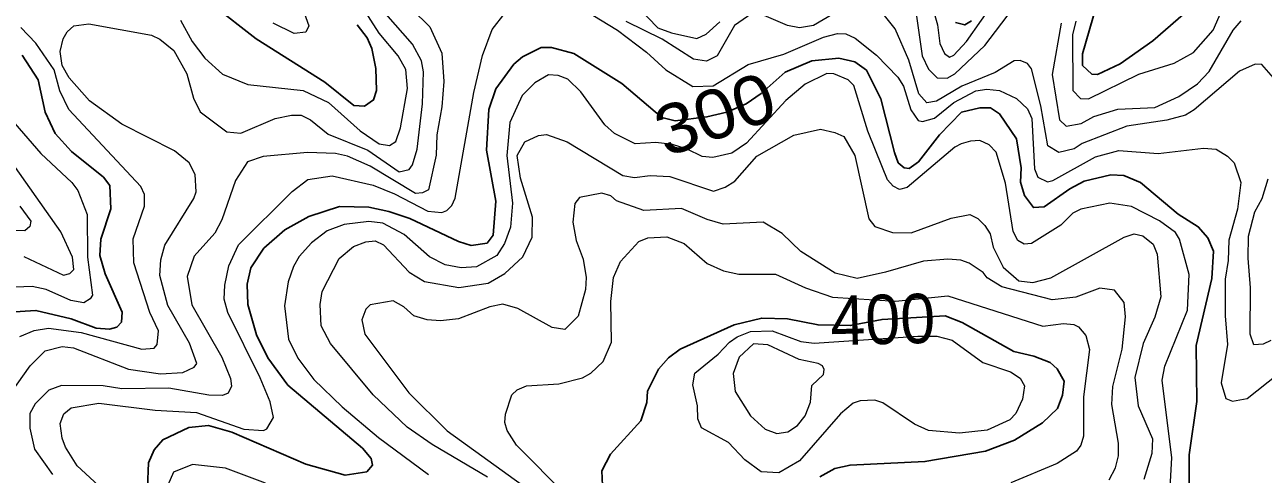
# Model space of a CAD drawing. Extents: x 673.6 to 698.9, y 7012 to 7040.1.
# Drawn here: x 691.831 to 693.836, y 7013.382 to 7014.11 of the extents above; entities that cross this region are included whole.
import ezdxf
from ezdxf.enums import TextEntityAlignment as Align

# ---------------------------------------------------------------- set-up
doc = ezdxf.new("R2010")
doc.units = 0
doc.header["$LTSCALE"] = 0.032
doc.layers.add('1', color=7, linetype='Continuous', lineweight=25)
doc.layers.add('2', color=7, linetype='Continuous', lineweight=13)
doc.layers.add('61', color=7, linetype='Continuous')

msp = doc.modelspace()

# ---------------------------------------------------------------- linework, layer by layer
at = {"layer": '1'}
for points in [[(693.7393, 7014.1557), (693.6572, 7014.0842), (693.6043, 7014.0469), (693.5677, 7014.0298), (693.5587, 7014.0301), (693.5438, 7014.0441), (693.5436, 7014.063), (693.5781, 7014.1829)], [(692.3692, 7014.1102), (692.3856, 7014.0888), (692.393, 7014.0715), (692.3996, 7014.0396), (692.4005, 7014.0035), (692.3956, 7013.9884), (692.3814, 7013.9783), (692.3638, 7013.9795), (692.3168, 7014.017), (692.2057, 7014.0872), (692.1352, 7014.1427)], [(693.3637, 7014.1164), (693.3529, 7014.11), (693.3378, 7014.1141)], [(693.0232, 7013.9989), (692.999, 7013.9821), (692.9679, 7013.9686), (692.9354, 7013.961), (692.884, 7013.9546), (692.8626, 7013.9598), (692.7977, 7014.015), (692.7201, 7014.0634), (692.684, 7014.0732), (692.6673, 7014.0732), (692.6371, 7014.0581), (692.623, 7014.0466), (692.594, 7014.0065), (692.5822, 7013.973), (692.5788, 7013.9068), (692.5936, 7013.8247), (692.5896, 7013.7694), (692.5796, 7013.7563), (692.5537, 7013.7529), (692.5336, 7013.7591), (692.4543, 7013.7962), (692.4207, 7013.8079), (692.3884, 7013.8146), (692.3405, 7013.816), (692.2909, 7013.7995), (692.2524, 7013.7779), (692.2183, 7013.7481), (692.1972, 7013.7165), (692.191, 7013.6899), (692.1925, 7013.657), (692.2064, 7013.6077), (692.2248, 7013.5709), (692.2571, 7013.5263), (692.3777, 7013.4246), (692.392, 7013.4079), (692.3939, 7013.3969), (692.3848, 7013.386), (692.35, 7013.3806), (692.2862, 7013.3986), (692.1664, 7013.4504), (692.1284, 7013.4612), (692.0966, 7013.4576), (692.0546, 7013.438), (692.0406, 7013.4215), (692.0317, 7013.4006), (692.0299, 7013.3608)], [(691.8269, 7014.0609), (691.853, 7014.0208), (691.864, 7013.9686), (691.8806, 7013.934), (691.9069, 7013.9051), (691.9585, 7013.8636), (691.9689, 7013.8497), (691.9707, 7013.8123), (691.9542, 7013.7631), (691.9527, 7013.7367), (691.9614, 7013.7069), (691.989, 7013.6447), (691.9875, 7013.6283), (691.9801, 7013.6204), (691.9685, 7013.617), (691.9465, 7013.6187), (691.906, 7013.6339), (691.8491, 7013.6476), (691.8065, 7013.6446)], [(693.7162, 7013.3668), (693.7162, 7013.4138), (693.7284, 7013.5001), (693.7277, 7013.5909), (693.7531, 7013.6994), (693.7555, 7013.7433), (693.7465, 7013.7651), (693.7309, 7013.7831), (693.6986, 7013.8032), (693.6372, 7013.8549), (693.6105, 7013.8662), (693.5895, 7013.867), (693.5461, 7013.8566), (693.523, 7013.8443), (693.4814, 7013.8155), (693.4641, 7013.814), (693.4495, 7013.8334), (693.4433, 7013.8555), (693.4441, 7013.8785), (693.4365, 7013.9255), (693.409, 7013.9661), (693.3944, 7013.9754), (693.3775, 7013.9754), (693.3477, 7013.9686), (693.312, 7013.932), (693.2778, 7013.8881), (693.2627, 7013.8772), (693.2547, 7013.8784), (693.2452, 7013.8867), (693.2394, 7013.9035), (693.2173, 7013.9902), (693.1936, 7014.0369), (693.175, 7014.0503), (693.1491, 7014.056), (693.1055, 7014.0516), (693.0624, 7014.0332), (693.0232, 7013.9989)], [(693.1183, 7013.3782), (693.1426, 7013.3912), (693.1672, 7013.3969), (693.2884, 7013.4027), (693.3867, 7013.4194), (693.4334, 7013.4373), (693.4789, 7013.4654), (693.503, 7013.4887), (693.5114, 7013.51), (693.5138, 7013.5329), (693.5024, 7013.553), (693.4912, 7013.5629), (693.465, 7013.5735), (693.4326, 7013.5807), (693.349, 7013.6282), (693.3214, 7013.6387), (693.2191, 7013.633), (693.1676, 7013.6229), (693.1156, 7013.6241), (693.0658, 7013.634), (693.0243, 7013.6352), (692.9797, 7013.624), (692.8924, 7013.5849), (692.8733, 7013.5706), (692.8569, 7013.5522), (692.8395, 7013.5169), (692.8383, 7013.4985), (692.8287, 7013.4688), (692.7796, 7013.4145), (692.7656, 7013.3875), (692.7667, 7013.3641)]]:
    msp.add_lwpolyline(points, dxfattribs=at)
at = {"layer": '2'}
for points in [[(692.3855, 7014.2132), (692.3997, 7014.1931), (692.4867, 7014.1069), (692.5064, 7014.0643), (692.5097, 7014.0182), (692.5065, 7013.9771)], [(693.2832, 7014.1987), (693.3086, 7014.1099), (693.3124, 7014.0799), (693.3203, 7014.0639), (693.3283, 7014.0578), (693.3351, 7014.0612), (693.3557, 7014.0833), (693.4043, 7014.1529)], [(692.7735, 7014.1908), (692.8562, 7014.1054), (692.878, 7014.0971), (692.9194, 7014.0882), (692.9341, 7014.095), (692.9566, 7014.1149)], [(693.261, 7014.1664), (693.274, 7014.1316), (693.2842, 7014.0597), (693.2942, 7014.0384), (693.3084, 7014.0242), (693.3246, 7014.0239)], [(692.0833, 7014.1176), (692.1019, 7014.083), (692.1225, 7014.0563), (692.1512, 7014.0299), (692.1923, 7014.0133), (692.2817, 7014.0036), (692.3227, 7013.9843), (692.3744, 7013.9382), (692.4049, 7013.9172), (692.4215, 7013.9147), (692.432, 7013.921), (692.4393, 7013.9434), (692.4506, 7014.0067), (692.4483, 7014.0378), (692.4356, 7014.0596), (692.4051, 7014.0968), (692.378, 7014.1386)], [(692.2758, 7014.151), (692.2911, 7014.1085), (692.286, 7014.098), (692.2672, 7014.0959), (692.2334, 7014.1129)], [(692.7382, 7014.1332), (692.791, 7014.1017), (692.8379, 7014.0656), (692.869, 7014.0371), (692.9128, 7014.01), (692.9456, 7014.0112), (693.0025, 7014.046), (693.0598, 7014.0628), (693.124, 7014.09), (693.1471, 7014.0961), (693.1605, 7014.0954), (693.1753, 7014.0887), (693.2102, 7014.0607), (693.2447, 7014.0255), (693.2537, 7014.0109), (693.2655, 7013.9726), (693.2776, 7013.9549), (693.2847, 7013.9535), (693.3042, 7013.9589), (693.3355, 7013.9841), (693.371, 7014.0034), (693.3885, 7014.0059), (693.4091, 7014.0037), (693.4367, 7013.991), (693.4544, 7013.974), (693.4613, 7013.9583), (693.4661, 7013.8766), (693.4714, 7013.8635), (693.4871, 7013.8557), (693.4953, 7013.8577), (693.5646, 7013.8965), (693.6024, 7013.9064), (693.6659, 7013.9016), (693.7395, 7013.9105), (693.7602, 7013.9086), (693.7783, 7013.8975), (693.7893, 7013.8864), (693.8, 7013.8548), (693.7943, 7013.8115), (693.7803, 7013.7615), (693.7795, 7013.7281), (693.7744, 7013.6982), (693.7745, 7013.639), (693.7785, 7013.5925), (693.7678, 7013.53), (693.7757, 7013.5048), (693.7865, 7013.5006), (693.8099, 7013.5048), (693.9094, 7013.5839)], [(693.3246, 7014.0239), (693.3368, 7014.0309), (693.3852, 7014.0768), (693.4304, 7014.1352)], [(693.5326, 7014.1162), (693.5276, 7014.0939), (693.528, 7014.0038), (693.5402, 7013.991), (693.5535, 7013.9902), (693.635, 7014.0302), (693.6921, 7014.0481), (693.7235, 7014.0651), (693.7553, 7014.1017), (693.7762, 7014.1497)], [(692.1052, 7013.5556), (692.1095, 7013.5616), (692.098, 7013.5946), (692.0626, 7013.6554), (692.0497, 7013.7043), (692.0513, 7013.7293), (692.0577, 7013.7533), (692.105, 7013.8287), (692.1087, 7013.8395), (692.1071, 7013.8675), (692.0971, 7013.8867), (692.0737, 7013.9062), (691.9882, 7013.9493), (691.9357, 7013.9869), (691.903, 7014.0241), (691.8919, 7014.044), (691.8887, 7014.0669), (691.8935, 7014.0872), (691.9, 7014.0987), (691.9108, 7014.1086), (691.9346, 7014.1118), (692.0361, 7014.0931), (692.05, 7014.087), (692.0725, 7014.0683), (692.0934, 7014.0306), (692.1041, 7013.9912), (692.1152, 7013.9693), (692.1585, 7013.9368), (692.1812, 7013.9346), (692.2366, 7013.9581), (692.2632, 7013.9639), (692.2785, 7013.9639), (692.2936, 7013.9563), (692.3224, 7013.9328), (692.3865, 7013.9072), (692.4372, 7013.8722), (692.4535, 7013.876), (692.4587, 7013.8834), (692.4663, 7013.9085), (692.4752, 7013.9821), (692.4768, 7014.0338), (692.4736, 7014.0516), (692.459, 7014.0788), (692.4156, 7014.128)], [(692.5879, 7014.1025), (692.6087, 7014.1294)], [(693.008, 7014.1283), (692.9802, 7014.1088), (692.9523, 7014.0601), (692.9351, 7014.0511), (692.9139, 7014.0545), (692.8628, 7014.0866), (692.8046, 7014.1156)], [(693.1393, 7014.1274), (693.1083, 7014.1088), (693.0854, 7014.1054), (693.066, 7014.1092), (693.0206, 7014.1283)], [(693.8528, 7014.0241), (693.8338, 7014.0459), (693.823, 7014.0461), (693.7977, 7014.035), (693.7246, 7013.9725), (693.7102, 7013.9636), (693.6803, 7013.9558), (693.6155, 7013.9458), (693.543, 7013.9176), (693.53, 7013.9093), (693.5054, 7013.9033), (693.4876, 7013.9142), (693.4761, 7013.9787), (693.4612, 7014.0387), (693.4545, 7014.0475), (693.4428, 7014.0525), (693.4328, 7014.0516), (693.402, 7014.0329), (693.348, 7014.0108), (693.3072, 7013.9863), (693.2913, 7013.9837), (693.2784, 7013.9982), (693.2624, 7014.053), (693.2405, 7014.1037), (693.2228, 7014.1253)], [(693.5089, 7014.1127), (693.4943, 7014.0294), (693.5065, 7013.9561), (693.5169, 7013.946), (693.5416, 7013.95), (693.562, 7013.9616), (693.6007, 7013.9737), (693.6605, 7013.9764), (693.6994, 7013.9942), (693.7295, 7014.0143), (693.7487, 7014.0347), (693.7875, 7014.1017), (693.8003, 7014.1164)], [(691.8231, 7013.6055), (691.8462, 7013.6148), (691.8696, 7013.6187), (691.9227, 7013.6115), (692.0209, 7013.5845), (692.0404, 7013.5865), (692.0454, 7013.5921), (692.0478, 7013.6144), (692.0334, 7013.6444), (692.0076, 7013.7244), (692.0069, 7013.7634), (692.0249, 7013.8161), (692.0249, 7013.8352), (692.0191, 7013.8484), (691.9026, 7013.9727), (691.8879, 7014.0031), (691.8786, 7014.0371), (691.8491, 7014.0806), (691.8247, 7014.1059)], [(692.5147, 7013.8095), (692.5226, 7013.8175), (692.528, 7013.8291), (692.5582, 7014.0006), (692.5723, 7014.0606), (692.5879, 7014.1025)], [(692.6571, 7014.016), (692.6364, 7013.9954), (692.6165, 7013.9521), (692.6117, 7013.8986), (692.6207, 7013.821), (692.6175, 7013.7823), (692.6079, 7013.756), (692.5952, 7013.7366), (692.5627, 7013.718), (692.5374, 7013.7167), (692.5118, 7013.7215), (692.4864, 7013.7341), (692.4455, 7013.7703), (692.4109, 7013.789), (692.388, 7013.7915), (692.3483, 7013.7867), (692.3205, 7013.7764), (692.2956, 7013.7572), (692.2756, 7013.7349), (692.2664, 7013.7188), (692.2578, 7013.6936), (692.2518, 7013.6547), (692.2583, 7013.6011), (692.273, 7013.5701), (692.2989, 7013.5355), (692.3448, 7013.4912), (692.404, 7013.4419), (692.4845, 7013.3819)], [(692.7705, 7013.9482), (692.7316, 7014.0016), (692.7102, 7014.0221), (692.6949, 7014.0282), (692.6793, 7014.0289), (692.6571, 7014.016)], [(693.6857, 7013.3608), (693.6882, 7013.4087), (693.6727, 7013.5345), (693.6769, 7013.5571), (693.7134, 7013.6477), (693.716, 7013.7059), (693.7008, 7013.7627), (693.6939, 7013.7738), (693.6681, 7013.7924), (693.6227, 7013.8159), (693.5876, 7013.821), (693.5407, 7013.8113), (693.5277, 7013.805), (693.5087, 7013.7854), (693.4611, 7013.756), (693.4493, 7013.7548), (693.439, 7013.7607), (693.4313, 7013.7753), (693.4187, 7013.8535), (693.4037, 7013.9039), (693.3927, 7013.9157), (693.3775, 7013.9227), (693.3621, 7013.9217), (693.3471, 7013.9173), (693.3369, 7013.9118), (693.2596, 7013.8468), (693.2475, 7013.8435), (693.237, 7013.8487), (693.2281, 7013.8591), (693.2195, 7013.8789), (693.1958, 7013.9381), (693.1732, 7014.0118), (693.1643, 7014.0208), (693.1409, 7014.0305), (693.1295, 7014.0312), (693.0946, 7014.0139), (693.0631, 7013.9873), (692.9998, 7013.9182), (692.9756, 7013.9024), (692.9449, 7013.895), (692.9279, 7013.8967), (692.9033, 7013.9088), (692.8796, 7013.9165), (692.8528, 7013.9194), (692.8194, 7013.9173), (692.7857, 7013.934), (692.7705, 7013.9482)], [(692.5065, 7013.9771), (692.4983, 7013.9319), (692.4973, 7013.8992), (692.4849, 7013.843), (692.4751, 7013.8377), (692.4638, 7013.8367), (692.3903, 7013.8811), (692.3539, 7013.8973), (692.3343, 7013.9015), (692.2888, 7013.9031), (692.2173, 7013.8968), (692.1917, 7013.8882), (692.1725, 7013.8582), (692.1504, 7013.7944), (692.1387, 7013.7729), (692.1055, 7013.7355), (692.094, 7013.7027), (692.1015, 7013.6564), (692.1504, 7013.5716), (692.1643, 7013.5373), (692.1661, 7013.5246), (692.1602, 7013.5136), (692.1511, 7013.5096), (692.1294, 7013.5104), (692.0644, 7013.5218), (691.9885, 7013.5203), (691.9579, 7013.5251), (691.8904, 7013.5259), (691.8702, 7013.5183), (691.8482, 7013.4961), (691.8394, 7013.4805), (691.8393, 7013.457), (691.8468, 7013.4229), (691.876, 7013.3816)], [(691.8152, 7013.9503), (691.8573, 7013.9015), (691.9072, 7013.8549), (691.917, 7013.8418), (691.9319, 7013.8027), (691.9325, 7013.734), (691.941, 7013.6723), (691.9372, 7013.6662), (691.9267, 7013.66), (691.9058, 7013.6638), (691.8659, 7013.6812), (691.8429, 7013.6862), (691.8162, 7013.6854)], [(692.5803, 7013.3773), (692.4907, 7013.4305), (692.45, 7013.4583), (692.3953, 7013.5106), (692.3262, 7013.5941), (692.311, 7013.6225), (692.3093, 7013.6573), (692.3127, 7013.6783), (692.34, 7013.7316), (692.3633, 7013.7511), (692.3832, 7013.7585), (692.3985, 7013.7601), (692.4118, 7013.7538), (692.4537, 7013.7095), (692.4785, 7013.6945), (692.5341, 7013.6846), (692.5813, 7013.6917), (692.6081, 7013.7074), (692.6373, 7013.7342), (692.6526, 7013.7664), (692.6534, 7013.7987), (692.6335, 7013.8618), (692.6282, 7013.8982), (692.6409, 7013.9208), (692.6627, 7013.9307), (692.6757, 7013.9327), (692.7092, 7013.9208), (692.7993, 7013.8663), (692.8182, 7013.8627)], [(692.8182, 7013.8627), (692.8434, 7013.866), (692.8754, 7013.8644), (692.9461, 7013.8408), (692.9651, 7013.8472), (692.9808, 7013.8567), (693.0161, 7013.8975), (693.0763, 7013.9315), (693.1195, 7013.9409), (693.1428, 7013.9359), (693.1573, 7013.9293), (693.1752, 7013.8982), (693.1974, 7013.7958), (693.2073, 7013.7834), (693.2357, 7013.7739), (693.2662, 7013.7732), (693.3308, 7013.7969), (693.3611, 7013.8029), (693.374, 7013.7966), (693.3857, 7013.7848), (693.3939, 7013.7718), (693.3991, 7013.75), (693.4151, 7013.7176), (693.4404, 7013.6953), (693.4634, 7013.6928), (693.4921, 7013.7004), (693.611, 7013.7659), (693.6272, 7013.7716), (693.6413, 7013.7683), (693.6582, 7013.7546), (693.6645, 7013.7388), (693.6702, 7013.6697), (693.6609, 7013.6366), (693.642, 7013.5939), (693.6281, 7013.5387), (693.6335, 7013.4927), (693.6569, 7013.4394), (693.6559, 7013.4155), (693.6428, 7013.3736)], [(691.8297, 7013.7346), (691.8937, 7013.7044), (691.9039, 7013.7071), (691.9104, 7013.714), (691.9082, 7013.7339), (691.8894, 7013.7746), (691.8164, 7013.8791)], [(691.9575, 7013.3575), (691.9159, 7013.396), (691.8969, 7013.4262), (691.8917, 7013.4405), (691.8887, 7013.4642), (691.8946, 7013.48), (691.9065, 7013.4896), (691.951, 7013.4972), (692.0422, 7013.4858), (692.1091, 7013.4824), (692.186, 7013.455), (692.2176, 7013.453), (692.2231, 7013.4556), (692.2336, 7013.474), (692.2283, 7013.4993), (692.2123, 7013.5384), (692.16, 7013.6444), (692.154, 7013.6658), (692.1549, 7013.6886), (692.1614, 7013.7195), (692.1772, 7013.7539), (692.2641, 7013.8399), (692.2896, 7013.8595), (692.329, 7013.8653), (692.395, 7013.8504), (692.4296, 7013.8365), (692.4839, 7013.8082), (692.5062, 7013.8062), (692.5147, 7013.8095)], [(693.8487, 7013.599), (693.8358, 7013.5926), (693.8208, 7013.5915), (693.8148, 7013.6091), (693.8156, 7013.6839), (693.8115, 7013.7322), (693.8124, 7013.7676), (693.8227, 7013.8071), (693.8343, 7013.8289), (693.8443, 7013.8605)], [(692.7889, 7013.8252), (692.7799, 7013.8331), (692.7653, 7013.8375), (692.7291, 7013.8302), (692.7218, 7013.8208), (692.7186, 7013.7907), (692.7238, 7013.7607), (692.735, 7013.7303), (692.7398, 7013.701), (692.7392, 7013.6815), (692.7273, 7013.6383), (692.7053, 7013.6168), (692.6851, 7013.62), (692.6292, 7013.6507), (692.6052, 7013.6574), (692.5838, 7013.6533), (692.5336, 7013.6338), (692.5044, 7013.6304), (692.4828, 7013.6321), (692.461, 7013.6386), (692.4449, 7013.6532), (692.4273, 7013.6632), (692.3902, 7013.6567), (692.3831, 7013.6497), (692.3766, 7013.6324), (692.3817, 7013.609), (692.4527, 7013.5139), (692.5151, 7013.4525), (692.6698, 7013.3408)], [(691.8231, 7013.8165), (691.8407, 7013.7921), (691.8394, 7013.7832), (691.8312, 7013.7765), (691.8167, 7013.7767)], [(693.5869, 7013.3729), (693.5972, 7013.3927), (693.6019, 7013.4121), (693.6019, 7013.4324), (693.5913, 7013.4951), (693.5929, 7013.5242), (693.6077, 7013.5847), (693.6133, 7013.6369), (693.611, 7013.6602), (693.5956, 7013.6801), (693.5714, 7013.6837), (693.5326, 7013.6687), (693.4946, 7013.6649), (693.4131, 7013.6858), (693.3893, 7013.7001), (693.383, 7013.7087), (693.3603, 7013.724), (693.3467, 7013.7288), (693.3257, 7013.7306), (693.2859, 7013.7274), (693.2244, 7013.7092), (693.179, 7013.6994), (693.1433, 7013.7081), (693.0877, 7013.7427), (693.0573, 7013.7723), (693.0267, 7013.7906), (692.962, 7013.787), (692.9357, 7013.7946), (692.8943, 7013.8127), (692.8336, 7013.8095), (692.7889, 7013.8252)], [(692.7084, 7013.3479), (692.6275, 7013.4294), (692.6123, 7013.4532), (692.6085, 7013.4661), (692.6093, 7013.4795), (692.6196, 7013.5106), (692.6285, 7013.5188), (692.6433, 7013.5251), (692.6959, 7013.5285), (692.7342, 7013.5381), (692.7475, 7013.5457), (692.7673, 7013.5648), (692.7809, 7013.5959), (692.7802, 7013.6619), (692.7842, 7013.7007), (692.7956, 7013.727), (692.8254, 7013.7593)], [(692.8254, 7013.7593), (692.8398, 7013.765), (692.8704, 7013.7666), (692.8989, 7013.7561), (692.9357, 7013.7236), (692.9624, 7013.7114), (692.9873, 7013.706), (693.0465, 7013.706), (693.0949, 7013.6839), (693.1389, 7013.669), (693.2408, 7013.6623), (693.3257, 7013.6712), (693.4791, 7013.6222), (693.5127, 7013.6262), (693.5297, 7013.6246), (693.5369, 7013.621), (693.5489, 7013.6071), (693.555, 7013.584), (693.5453, 7013.5078), (693.5453, 7013.4437), (693.5411, 7013.4293), (693.5339, 7013.4197), (693.5026, 7013.3994), (693.4275, 7013.3684)], [(691.7909, 7013.4893), (691.8401, 7013.5575), (691.8641, 7013.5822), (691.8915, 7013.5891)], [(691.8915, 7013.5891), (691.9099, 7013.5868), (691.9991, 7013.5526), (692.0509, 7013.5447), (692.0869, 7013.5469), (692.1052, 7013.5556)], [(692.2208, 7013.3678), (692.1561, 7013.3921), (692.1027, 7013.3979), (692.0719, 7013.3854), (692.0628, 7013.3642)]]:
    msp.add_lwpolyline(points, dxfattribs=at)
for points in [[(693.2772, 7013.606), (693.3078, 7013.606), (693.3323, 7013.5994), (693.382, 7013.5631), (693.4268, 7013.5481), (693.4428, 7013.5378), (693.4498, 7013.5255), (693.4465, 7013.5038), (693.4357, 7013.4806), (693.426, 7013.4703), (693.3894, 7013.4537), (693.3443, 7013.4488), (693.2942, 7013.4532), (693.2718, 7013.4635), (693.2204, 7013.498), (693.2075, 7013.5022), (693.1836, 7013.5013), (693.1722, 7013.4972), (693.1518, 7013.4802), (693.0852, 7013.4039), (693.0518, 7013.3846), (693.0235, 7013.3861), (692.9971, 7013.4055), (692.9706, 7013.4334), (692.927, 7013.4571), (692.9207, 7013.4721), (692.9205, 7013.4931), (692.9125, 7013.5268), (692.9158, 7013.5456), (692.9538, 7013.5764), (692.9719, 7013.5959), (692.9847, 7013.6048), (693.0062, 7013.6131), (693.0414, 7013.6146), (693.0878, 7013.5972), (693.1089, 7013.5942)], [(693.0059, 7013.4769), (693.0298, 7013.455), (693.0485, 7013.448), (693.0663, 7013.451), (693.082, 7013.4613), (693.0944, 7013.4768), (693.1031, 7013.4989), (693.1052, 7013.5257), (693.1241, 7013.5438), (693.1253, 7013.5516), (693.1224, 7013.5576), (693.1158, 7013.5617), (693.0848, 7013.5681), (693.0343, 7013.5916), (693.011, 7013.5935), (692.9876, 7013.5718), (692.9782, 7013.5453), (692.9813, 7013.516)]]:
    msp.add_lwpolyline(points, close=True, dxfattribs=at)

# ---------------------------------------------------------------- texts
at = {"layer": '61'}
for s, rotation, width, p in [('300', 19.358, 1.1, (692.9619, 7013.9279)), ('400', 1.444, 0.95, (693.2211, 7013.593))]:
    msp.add_text(s, height=0.08, rotation=rotation, dxfattribs=dict(at, width=width)).set_placement(p, align=Align.CENTER)

doc.saveas('drawing.dxf')
